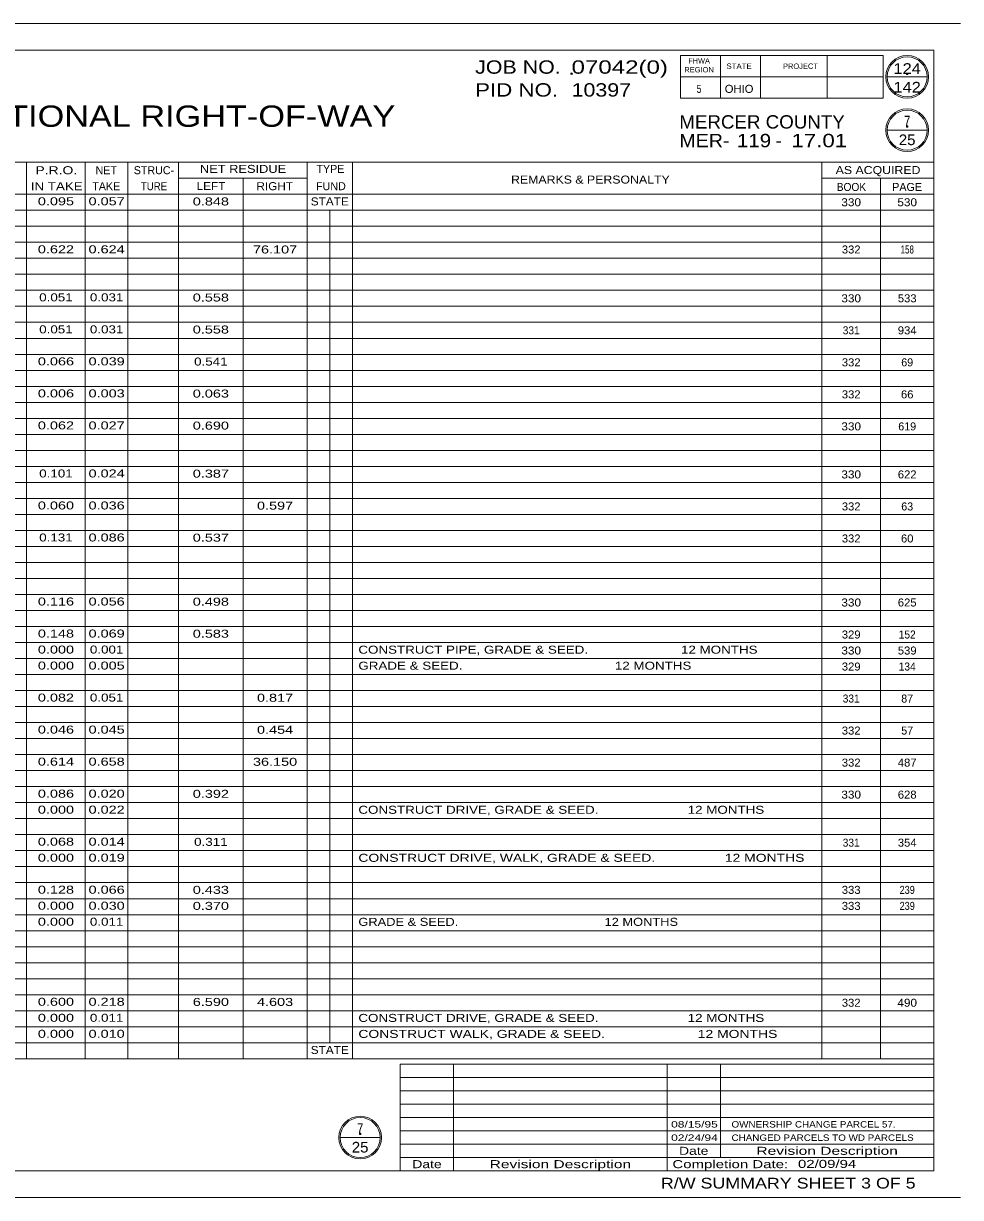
# Model space of a CAD drawing. Extents: x -1 to 34.5, y 0 to 22.
# Drawn here: x 16.94 to 34.5, y 0 to 22 of the extents above; entities that cross this region are included whole.
import ezdxf
from ezdxf.enums import TextEntityAlignment as Align

# ---------------------------------------------------------------- set-up
doc = ezdxf.new("R2010")
doc.units = 0
doc.header["$LTSCALE"] = 0.06
doc.header["$PDMODE"] = 32
doc.header["$PDSIZE"] = 0.03
doc.layers.add('1', color=7, linetype='Continuous', lineweight=13)

msp = doc.modelspace()

# ---------------------------------------------------------------- linework, layer by layer
at = {"layer": '1'}
for p, q in [((-1, 22), (34.5, 22)), ((0.5, 21.5), (34, 21.5)), ((30, 21.4), (30, 20.6)), ((30.75, 21.4), (30.75, 20.6)), ((32.002, 21.4), (32.002, 20.6)), ((29.25, 21), (33.05, 21)), ((33.125, 21), (33.875, 21)), ((33.125, 20.00258), (33.875, 20.00258)), ((0.5, 19.4), (34, 19.4)), ((16.99617, 2.6), (16.99617, 19.4)), ((18.09617, 2.6), (18.09617, 19.4)), ((18.89617, 2.6), (18.89617, 19.4)), ((19.84617, 2.6), (19.84617, 19.4)), ((22.253, 2.6), (22.253, 19.4)), ((23.103, 2.6), (23.103, 19.4)), ((31.90092, 2.6), (31.90092, 19.4)), ((19.853, 19.1), (22.253, 19.1)), ((21.053, 2.6), (21.053, 19.1)), ((31.90092, 19.1), (34, 19.1)), ((33.00092, 2.6), (33.00092, 19.1)), ((33.00092, 2.6), (33.00092, 19.1)), ((0.5, 18.8), (34, 18.8)), ((0.5, 18.5), (34, 18.5)), ((22.68042, 18.5), (22.68042, 2.9)), ((0.5, 18.2), (34, 18.2)), ((0.5, 17.9), (34, 17.9)), ((0.5, 17.6), (34, 17.6)), ((0.5, 17.3), (34, 17.3)), ((0.5, 17), (34, 17)), ((0.5, 16.7), (34, 16.7)), ((0.5, 16.4), (34, 16.4)), ((0.5, 16.1), (34, 16.1)), ((0.5, 15.8), (34, 15.8)), ((0.5, 15.5), (34, 15.5)), ((0.5, 15.2), (34, 15.2)), ((0.5, 14.9), (34, 14.9)), ((0.5, 14.6), (34, 14.6)), ((0.5, 14.3), (34, 14.3)), ((0.5, 14), (34, 14)), ((0.5, 13.7), (34, 13.7)), ((0.5, 13.4), (34, 13.4)), ((0.5, 13.1), (34, 13.1)), ((0.5, 12.8), (34, 12.8)), ((0.5, 12.5), (34, 12.5)), ((0.5, 12.2), (34, 12.2)), ((0.5, 11.9), (34, 11.9)), ((0.5, 11.6), (34, 11.6)), ((0.5, 11.3), (34, 11.3)), ((0.5, 11), (34, 11)), ((0.5, 10.7), (34, 10.7)), ((0.5, 10.4), (34, 10.4)), ((0.5, 10.1), (34, 10.1)), ((0.5, 9.8), (34, 9.8)), ((0.5, 9.5), (34, 9.5)), ((0.5, 9.2), (34, 9.2)), ((0.5, 8.9), (34, 8.9)), ((0.5, 8.6), (34, 8.6)), ((0.5, 8.3), (34, 8.3)), ((0.5, 8), (34, 8)), ((0.5, 7.7), (34, 7.7)), ((0.5, 7.4), (34, 7.4)), ((0.5, 7.1), (34, 7.1)), ((0.5, 6.8), (34, 6.8)), ((0.5, 6.5), (34, 6.5)), ((0.5, 6.2), (34, 6.2)), ((0.5, 5.9), (34, 5.9)), ((0.5, 5.6), (34, 5.6)), ((0.5, 5.3), (34, 5.3)), ((0.5, 5), (34, 5)), ((0.5, 4.7), (34, 4.7)), ((0.5, 4.4), (34, 4.4)), ((0.5, 4.1), (34, 4.1)), ((0.5, 3.8), (34, 3.8)), ((0.5, 3.5), (34, 3.5)), ((0.5, 3.2), (34, 3.2)), ((0.5, 2.9), (34, 2.9)), ((0.5, 2.6), (34, 2.6)), ((34, 2.6), (22, 2.6)), ((34, 2.5), (24, 2.5)), ((24, 2.5), (24, 0.5)), ((25, 2.5), (25, 0.5)), ((29, 2.5), (29, 0.5)), ((30, 2.5), (30, 0.75)), ((34, 2.25), (24, 2.25)), ((34, 2), (24, 2)), ((34, 1.75), (24, 1.75)), ((34, 1.5), (24, 1.5)), ((22.87275, 1.12558), (23.62267, 1.12558)), ((34, 1.25), (24, 1.25)), ((34, 1), (24, 1)), ((34, 0.75), (24, 0.75)), ((-1, 0), (34.5, 0))]:
    msp.add_line(p, q, dxfattribs=at)
msp.add_lwpolyline([(34, 21.5), (34, 0.5), (0.5, 0.5)], dxfattribs=at)
msp.add_lwpolyline([(29.25, 20.6), (33.05, 20.6), (33.05, 21.4), (29.25, 21.4)], close=True, dxfattribs=at)
for centre, radius in [((33.5, 21), 0.4), ((33.5, 21), 0.375), ((33.5, 20), 0.4), ((33.5, 20), 0.375), ((23.24771, 1.12305), 0.4), ((23.24771, 1.12305), 0.375)]:
    msp.add_circle(centre, radius, dxfattribs=at)
for p in [(27.21, 21.05892), (33.5, 21.05592), (33.5, 20.07), (23.24775, 1.19308)]:
    msp.add_point(p, dxfattribs=at)

# ---------------------------------------------------------------- texts
for s, height, width, p in [('FHWA', 0.1, 0.95, (29.60004, 21.25)), ('REGION', 0.1, 1.05, (29.6, 21.08333)), ('STATE', 0.1, 1.1, (30.35, 21.15)), ('PROJECT', 0.1, 1.05, (31.50004, 21.15)), ('124', 0.2, 1.15, (33.5, 21.05592)), ('142', 0.2, 1.15, (33.5, 20.70592)), ('5', 0.15, 0.8, (29.6, 20.7)), ('OHIO', 0.15, 1.05, (30.35004, 20.7)), ('SUMMARY OF ADDITIONAL RIGHT-OF-WAY', 0.4, 1.2, (17.2385, 20.06342)), ('7', 0.2, 0.8, (33.5, 20.07)), ('119', 0.25, 1.15, (30.62958, 19.68125)), ('25', 0.2, 1.05, (33.49996, 19.72)), ('P.R.O.', 0.15, 1.3, (17.55308, 19.175)), ('NET RESIDUE', 0.15, 1.2, (21.05304, 19.2)), ('REMARKS & PERSONALTY', 0.15, 1.15, (27.56296, 19)), ('AS ACQUIRED', 0.15, 1.15, (32.95442, 19.17858)), ('IN TAKE', 0.15, 1.25, (17.56058, 18.875)), ('LEFT', 0.15, 1.1, (20.45296, 18.87867)), ('RIGHT', 0.15, 1.1, (21.64696, 18.87642)), ('BOOK', 0.15, 0.95, (32.45529, 18.86167)), ('0.095', 0.15, 1.35, (17.54612, 18.59317)), ('0.057', 0.15, 1.35, (18.49612, 18.59317)), ('0.848', 0.15, 1.35, (20.44963, 18.59)), ('STATE', 0.15, 1.1, (22.678, 18.59)), ('330', 0.15, 1.1, (32.45087, 18.575)), ('530', 0.15, 1.1, (33.50046, 18.575)), ('0.622', 0.15, 1.35, (17.54612, 17.69317)), ('0.624', 0.15, 1.35, (18.49612, 17.69317)), ('76.107', 0.15, 1.35, (21.65304, 17.69)), ('332', 0.15, 1.05, (32.45087, 17.69)), ('158', 0.15, 0.75, (33.50092, 17.69)), ('0.051', 0.15, 1.25, (17.54617, 16.79317)), ('0.031', 0.15, 1.25, (18.49617, 16.79317)), ('0.558', 0.15, 1.35, (20.44963, 16.79)), ('330', 0.15, 1.1, (32.45087, 16.775)), ('533', 0.15, 1.05, (33.50046, 16.775)), ('0.051', 0.15, 1.25, (17.54617, 16.19317)), ('0.031', 0.15, 1.25, (18.49617, 16.19317)), ('0.558', 0.15, 1.35, (20.44963, 16.19)), ('331', 0.15, 0.95, (32.45092, 16.175)), ('934', 0.15, 1.05, (33.50046, 16.175)), ('0.066', 0.15, 1.35, (17.54621, 15.59317)), ('0.039', 0.15, 1.35, (18.49612, 15.59317)), ('0.541', 0.15, 1.25, (20.44967, 15.59)), ('332', 0.15, 1.05, (32.45087, 15.575)), ('0.006', 0.15, 1.35, (17.54621, 14.99317)), ('0.003', 0.15, 1.35, (18.49612, 14.99317)), ('0.063', 0.15, 1.35, (20.44963, 14.99)), ('332', 0.15, 1.05, (32.45087, 14.975)), ('66', 0.15, 1.05, (33.5005, 14.975)), ('0.062', 0.15, 1.35, (17.54612, 14.39317)), ('0.027', 0.15, 1.35, (18.49612, 14.39317)), ('0.690', 0.15, 1.35, (20.44971, 14.39)), ('330', 0.15, 1.1, (32.45087, 14.375)), ('0.101', 0.15, 1.25, (17.54617, 13.49317)), ('0.024', 0.15, 1.35, (18.49612, 13.49317)), ('0.387', 0.15, 1.35, (20.44963, 13.49)), ('330', 0.15, 1.1, (32.45087, 13.475)), ('622', 0.15, 1.05, (33.5005, 13.475)), ('0.060', 0.15, 1.35, (17.54621, 12.89317)), ('0.036', 0.15, 1.35, (18.49621, 12.89317)), ('0.597', 0.15, 1.35, (21.65296, 12.89)), ('332', 0.15, 1.05, (32.45087, 12.875)), ('0.131', 0.15, 1.25, (17.54617, 12.29317)), ('0.086', 0.15, 1.35, (18.49621, 12.29317)), ('0.537', 0.15, 1.35, (20.44963, 12.29)), ('332', 0.15, 1.05, (32.45087, 12.275)), ('60', 0.15, 1.05, (33.5005, 12.275)), ('0.116', 0.15, 1.35, (17.54621, 11.09317)), ('0.056', 0.15, 1.35, (18.49621, 11.09317)), ('0.498', 0.15, 1.35, (20.44963, 11.09)), ('330', 0.15, 1.1, (32.45087, 11.075)), ('625', 0.15, 1.05, (33.5005, 11.075)), ('0.148', 0.15, 1.35, (17.54612, 10.49317)), ('0.069', 0.15, 1.35, (18.49612, 10.49317)), ('0.583', 0.15, 1.35, (20.44963, 10.49)), ('329', 0.15, 1.05, (32.45096, 10.475)), ('152', 0.15, 0.95, (33.5005, 10.475)), ('0.000', 0.15, 1.35, (17.54621, 10.19317)), ('0.001', 0.15, 1.25, (18.49617, 10.19317)), ('330', 0.15, 1.1, (32.45087, 10.175)), ('539', 0.15, 1.05, (33.50054, 10.175)), ('0.000', 0.15, 1.35, (17.54621, 9.89317)), ('0.005', 0.15, 1.35, (18.49612, 9.89317)), ('329', 0.15, 1.05, (32.45096, 9.875)), ('134', 0.15, 0.95, (33.5005, 9.875)), ('0.082', 0.15, 1.35, (17.54612, 9.29317)), ('0.051', 0.15, 1.25, (18.49617, 9.29317)), ('0.817', 0.15, 1.35, (21.65296, 9.29)), ('331', 0.15, 0.95, (32.45092, 9.275)), ('0.046', 0.15, 1.35, (17.54621, 8.69317)), ('0.045', 0.15, 1.35, (18.49612, 8.69317)), ('0.454', 0.15, 1.35, (21.65296, 8.69)), ('332', 0.15, 1.05, (32.45087, 8.675)), ('0.614', 0.15, 1.35, (17.54612, 8.09317)), ('0.658', 0.15, 1.35, (18.49612, 8.09317)), ('36.150', 0.15, 1.35, (21.65296, 8.09)), ('332', 0.15, 1.05, (32.45087, 8.075)), ('487', 0.15, 1.05, (33.50046, 8.075)), ('0.086', 0.15, 1.35, (17.54621, 7.49317)), ('0.020', 0.15, 1.35, (18.49621, 7.49317)), ('0.392', 0.15, 1.35, (20.44963, 7.49)), ('330', 0.15, 1.1, (32.45087, 7.475)), ('628', 0.15, 1.05, (33.5005, 7.475)), ('0.000', 0.15, 1.35, (17.54621, 7.19317)), ('0.022', 0.15, 1.35, (18.49612, 7.19317)), ('0.068', 0.15, 1.35, (17.54612, 6.59317)), ('0.014', 0.15, 1.35, (18.49612, 6.59317)), ('0.311', 0.15, 1.25, (20.44967, 6.59)), ('331', 0.15, 0.95, (32.45092, 6.575)), ('354', 0.15, 1.05, (33.50046, 6.575)), ('0.000', 0.15, 1.35, (17.54621, 6.29317)), ('0.019', 0.15, 1.35, (18.49612, 6.29317)), ('0.128', 0.15, 1.35, (17.54612, 5.69317)), ('0.066', 0.15, 1.35, (18.49621, 5.69317)), ('0.433', 0.15, 1.35, (20.44963, 5.69)), ('333', 0.15, 1.05, (32.45087, 5.69)), ('239', 0.15, 0.85, (33.50096, 5.69)), ('0.000', 0.15, 1.35, (17.54621, 5.39317)), ('0.030', 0.15, 1.35, (18.49621, 5.39317)), ('0.370', 0.15, 1.35, (20.44971, 5.39)), ('333', 0.15, 1.05, (32.45087, 5.39)), ('239', 0.15, 0.85, (33.50096, 5.39)), ('0.000', 0.15, 1.35, (17.54621, 5.09317)), ('0.011', 0.15, 1.25, (18.49617, 5.09317)), ('0.600', 0.15, 1.35, (17.54621, 3.59317)), ('0.218', 0.15, 1.35, (18.49612, 3.59317)), ('6.590', 0.15, 1.35, (20.44971, 3.59)), ('4.603', 0.15, 1.35, (21.65296, 3.59)), ('332', 0.15, 1.05, (32.45087, 3.575)), ('490', 0.15, 1.1, (33.50046, 3.575)), ('0.000', 0.15, 1.35, (17.54621, 3.29317)), ('0.011', 0.15, 1.25, (18.49617, 3.29317)), ('0.000', 0.15, 1.35, (17.54621, 2.99317)), ('0.010', 0.15, 1.35, (18.49621, 2.99317)), ('STATE', 0.15, 1.1, (22.678, 2.69)), ('7', 0.2, 0.8, (23.24775, 1.19308)), ('25', 0.2, 1.05, (23.24771, 0.84308)), ('Date', 0.15, 1.3, (29.5, 0.8)), ('Revision Description', 0.15, 1.45, (32, 0.8)), ('Date', 0.15, 1.3, (24.5, 0.55)), ('Revision Description', 0.15, 1.45, (27, 0.55))]:
    msp.add_text(s, height=height, dxfattribs=dict(at, width=width)).set_placement(p, align=Align.CENTER)
for s, height, width, p in [('JOB NO.', 0.25, 1.2, (25.40233, 21.05892)), ('07042(0)', 0.25, 1.35, (27.21, 21.05892)), ('PID NO.', 0.25, 1.25, (25.40233, 20.63033)), ('10397', 0.25, 1.2, (27.21, 20.63033)), ('MERCER COUNTY', 0.25, 1.05, (29.22958, 20.03125)), ('MER-', 0.25, 1.1, (29.22958, 19.68125)), ('17.01', 0.25, 1.25, (31.32958, 19.68125)), ('-', 0.25, 1.1, (31.02958, 19.68125)), ('TURE', 0.15, 0.9, (19.13825, 18.87483)), ('CONSTRUCT PIPE, GRADE & SEED.                         12 MONTHS', 0.15, 1.25, (23.21425, 10.19067)), ('GRADE & SEED.                                         12 MONTHS                            ', 0.15, 1.25, (23.21425, 9.89067)), ('CONSTRUCT DRIVE, GRADE & SEED.                        12 MONTHS', 0.15, 1.25, (23.21425, 7.19067)), ('CONSTRUCT DRIVE, WALK, GRADE & SEED.                  12 MONTHS', 0.15, 1.3, (23.21425, 6.29067)), ('GRADE & SEED.                                         12 MONTHS', 0.15, 1.2, (23.21425, 5.09067)), ('CONSTRUCT DRIVE, GRADE & SEED.                        12 MONTHS', 0.15, 1.25, (23.21425, 3.29067)), ('CONSTRUCT WALK, GRADE & SEED.                        12 MONTHS', 0.15, 1.3, (23.21425, 2.99067)), ('08/15/95', 0.12, 1.4, (29.07608, 1.3115)), ('OWNERSHIP CHANGE PARCEL 57.', 0.12, 1.15, (30.20767, 1.3115)), ('02/24/94', 0.12, 1.4, (29.07608, 1.0615)), ('CHANGED PARCELS TO WD PARCELS', 0.12, 1.15, (30.20767, 1.0615)), ('Completion Date:', 0.15, 1.4, (29.1, 0.55)), ('02/09/94', 0.15, 1.4, (31.45275, 0.555))]:
    msp.add_text(s, height=height, dxfattribs=dict(at, width=width)).set_placement(p)
for s, p in [('NET', (18.48912, 19.175)), ('STRUC-', (19.38237, 19.17558)), ('TYPE', (22.691, 19.2)), ('TAKE', (18.48908, 18.875)), ('FUND', (22.69962, 18.87642)), ('PAGE', (33.49883, 18.86167)), ('PAGE', (33.49883, 18.86167)), ('69', (33.50046, 15.575)), ('619', (33.50054, 14.375)), ('63', (33.50054, 12.875)), ('87', (33.50046, 9.275)), ('57', (33.50046, 8.675))]:
    msp.add_text(s, height=0.15, dxfattribs=at).set_placement(p, align=Align.CENTER)
at = {"layer": '1', "width": 1.25}
msp.add_text('R/W SUMMARY SHEET 3 OF 5', height=0.2, dxfattribs=at).set_placement((33.65833, 0.16892), align=Align.RIGHT)

doc.saveas('drawing.dxf')
